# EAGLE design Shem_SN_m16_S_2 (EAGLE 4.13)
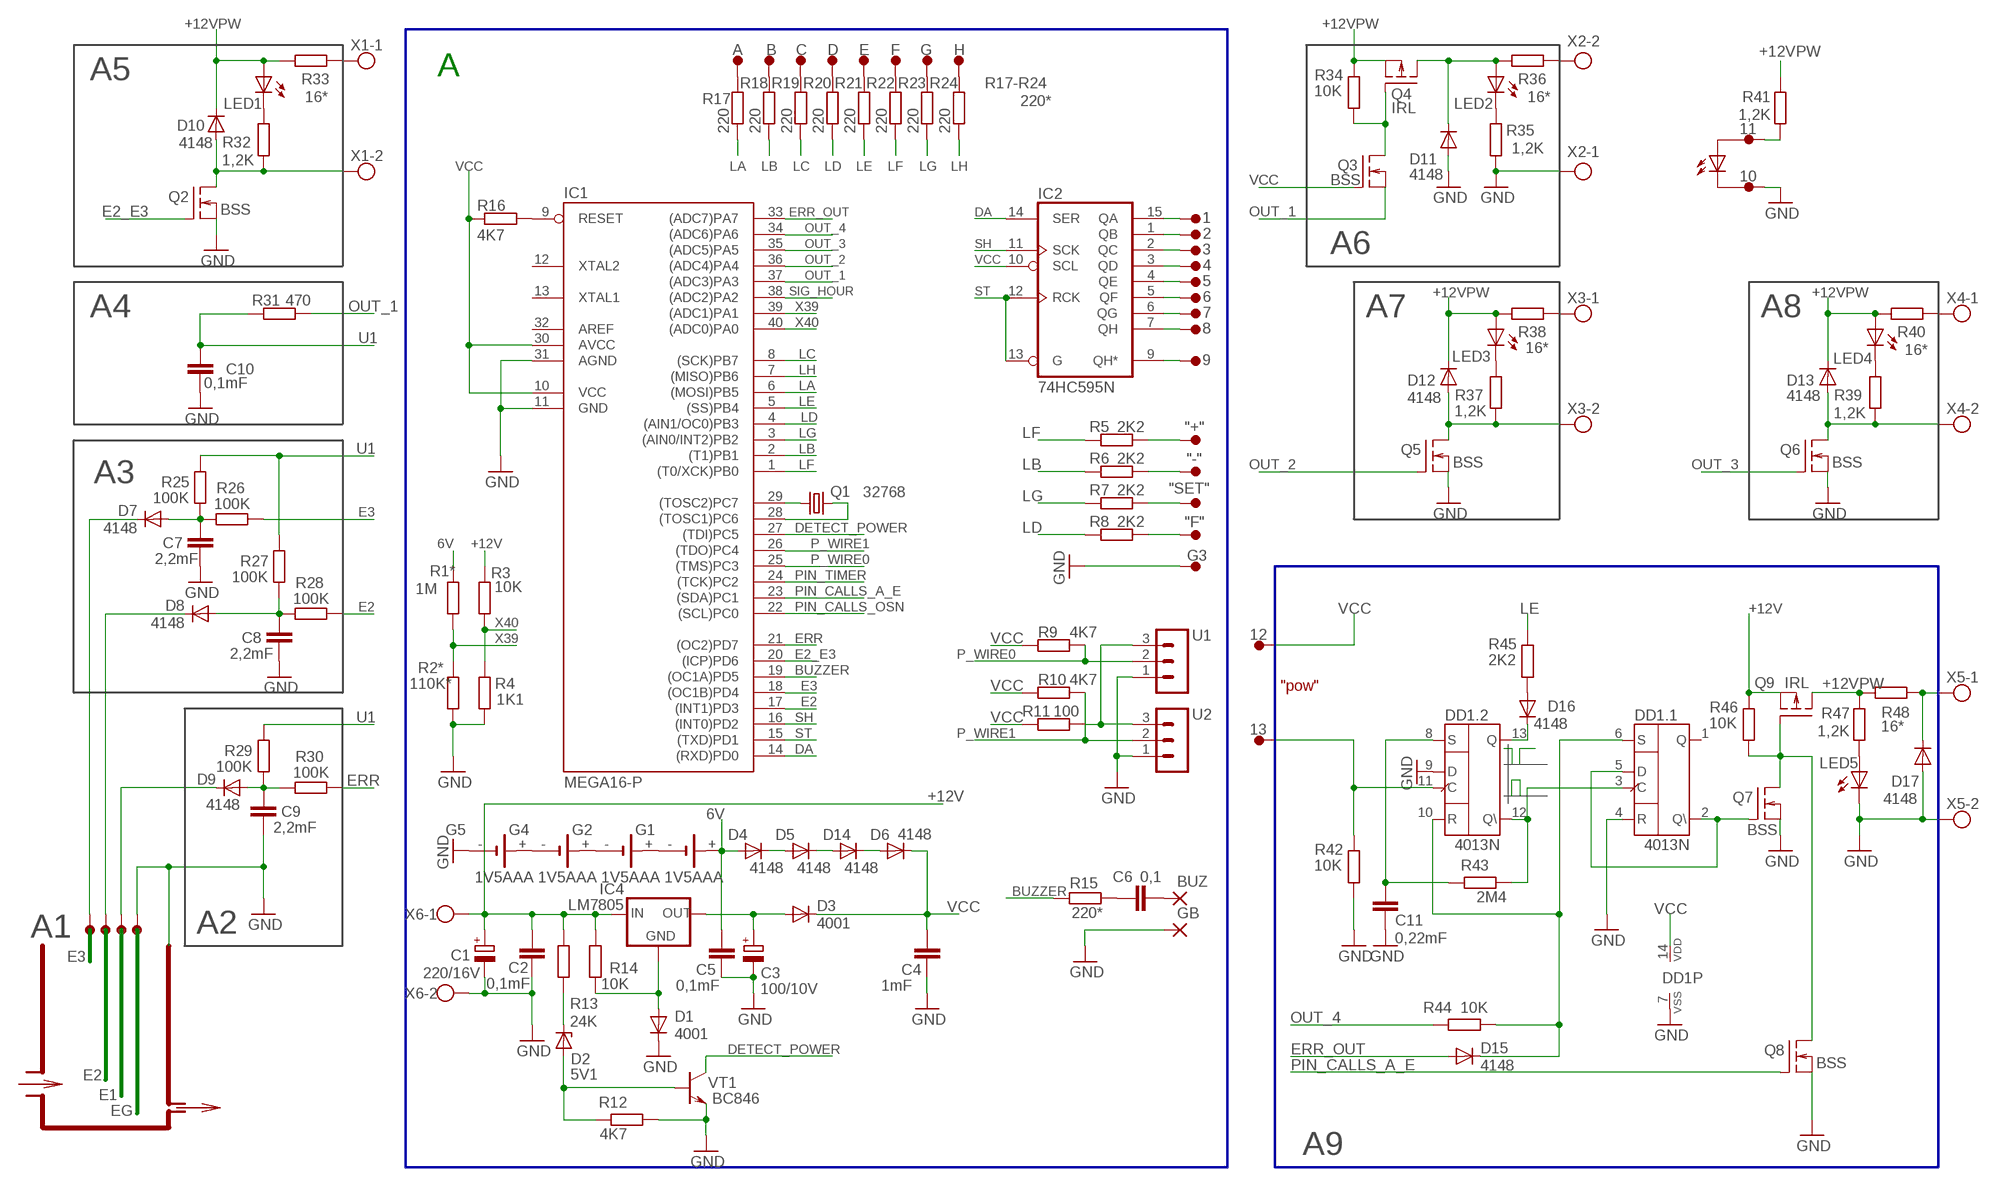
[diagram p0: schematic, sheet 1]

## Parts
1  2,0/0,8  [2,0/0,8]
2  2,0/0,8  [2,0/0,8]
3  2,0/0,8  [2,0/0,8]
4  2,0/0,8  [2,0/0,8]
5  2,0/0,8  [2,0/0,8]
6  2,0/0,8  [2,0/0,8]
7  2,0/0,8  [2,0/0,8]
8  2,0/0,8  [2,0/0,8]
9  2,0/0,8  [2,0/0,8]
10  2,0/0,8  [2,0/0,8]
11  2,0/0,8  [2,0/0,8]
12  2,0/0,8  [2,0/0,8]
13  2,0/0,8  [2,0/0,8]
"+"  2,0/0,8  [2,0/0,8]
"-"  2,0/0,8  [2,0/0,8]
"F"  2,0/0,8  [2,0/0,8]
"SET"  2,0/0,8  [2,0/0,8]
A  2,0/0,8  [2,0/0,8]
B  2,0/0,8  [2,0/0,8]
BUZ  2,15/1,0  [2,15/1,0]
C  2,0/0,8  [2,0/0,8]
C1  220/16V  CPOL-EUE2.5-5  [E2,5-5]
C2  0,1mF  C-EU050-024X044  [C050-024X044]
C3  100/10V  CPOL-EUE2.5-5  [E2,5-5]
C4  1mF  C-EU050-024X044  [C050-024X044]
C5  0,1mF  C-EU050-024X044  [C050-024X044]
C6  0,1  C-EU050-024X044  [C050-024X044]
C7  2,2mF  C-EU050-024X044  [C050-024X044]
C8  2,2mF  C-EU050-024X044  [C050-024X044]
C9  2,2mF  C-EU050-024X044  [C050-024X044]
C10  0,1mF  C-EU050-024X044  [C050-024X044]
C11  0,22mF  C-EU050-024X044  [C050-024X044]
D  2,0/0,8  [2,0/0,8]
D1  4001  [D041-7,62]
D2  5V1  BZX90  [DO34Z7]
D3  4001  [D041-7,62]
D4  4148  BAS15  [DO34-7]
D5  4148  BAS15  [DO34-7]
D6  4148  BAS15  [DO34-7]
D7  4148  BAS15  [DO34-7]
D8  4148  BAS15  [DO34-7]
D9  4148  BAS15  [DO34-7]
D10  4148  BAS15  [DO34-7]
D11  4148  BAS15  [DO34-7]
D12  4148  BAS15  [DO34-7]
D13  4148  BAS15  [DO34-7]
D14  4148  BAS15  [DO34-7]
D15  4148  BAS15  [DO34-7]
D16  4148  BAS15  [DO34-7]
D17  4148  BAS15  [DO34-7]
DD1  4013N  [DIL14]
E  2,0/0,8  [2,0/0,8]
E1  2,15/0,8  [2,15/1,0]
E2  2,15/0,8  [2,15/1,0]
E3  2,15/0,8  [2,15/1,0]
EG  2,15/0,8  [2,15/1,0]
F  2,0/0,8  [2,0/0,8]
G  2,0/0,8  [2,0/0,8]
G1  1V5AAA  [R1,5GAAA]
G2  1V5AAA  [R1,5GAAA]
G3  2,0/0,8  [2,0/0,8]
G4  1V5AAA  [R1,5GAAA]
G5  1V5AAA  [R1,5GAAA]
GB  2,15/1,0  [2,15/1,0]
H  2,0/0,8  [2,0/0,8]
IC1  MEGA16-P  [DIL40]
IC2  74HC595N  [DIL16]
IC4  LM7805  78XXL  [78XXL]
LED1  LED3MM  [LED3MM]
LED2  LED3MM  [LED3MM]
LED3  LED3MM  [LED3MM]
LED4  LED3MM  [LED3MM]
LED5  LED3MM  [LED3MM]
Q1  32768  CRYSTALTC26V  [TC26V]
Q2  BSS  MOSFET-NGSD  [MICRO3]
Q3  BSS  MOSFET-NGSD  [MICRO3]
Q4  IRL  MOSFET-PGSD  [MICRO3]
Q5  BSS  MOSFET-NGSD  [MICRO3]
Q6  BSS  MOSFET-NGSD  [MICRO3]
Q7  BSS  MOSFET-NGSD  [MICRO3]
Q8  BSS  MOSFET-NGSD  [MICRO3]
Q9  IRL  MOSFET-PGSD  [MICRO3]
R1*  1M  R0.25-10.16  [0.25W-10.16]
R2*  110K*  R0.25-10.16  [0.25W-10.16]
R3  10K  R0.25-10.16  [0.25W-10.16]
R4  1K1  R0.25-10.16  [0.25W-10.16]
R5  2K2  R0.25-10.16  [0.25W-10.16]
R6  2K2  R0.25-10.16  [0.25W-10.16]
R7  2K2  R0.25-10.16  [0.25W-10.16]
R8  2K2  R0.25-10.16  [0.25W-10.16]
R9  4K7  R0.25-10.16  [0.25W-10.16]
R10  4K7  R0.25-10.16  [0.25W-10.16]
R11  100  R0.25-10.16  [0.25W-10.16]
R12  4K7  R0.25-10.16  [0.25W-10.16]
R13  24K  R0.25-10.16  [0.25W-10.16]
R14  10K  R0.25-10.16  [0.25W-10.16]
R15  220*  R0.25-10.16  [0.25W-10.16]
R16  4K7  R0.25-10.16  [0.25W-10.16]
R17  220  R0.25-10.16  [0.25W-10.16]
R18  220  R0.25-10.16  [0.25W-10.16]
R19  220  R0.25-10.16  [0.25W-10.16]
R20  220  R0.25-10.16  [0.25W-10.16]
R21  220  R0.25-10.16  [0.25W-10.16]
R22  220  R0.25-10.16  [0.25W-10.16]
R23  220  R0.25-10.16  [0.25W-10.16]
R24  220  R0.25-10.16  [0.25W-10.16]
R25  100K  R0.25-10.16  [0.25W-10.16]
R26  100K  R0.25-10.16  [0.25W-10.16]
R27  100K  R0.25-10.16  [0.25W-10.16]
R28  100K  R0.25-10.16  [0.25W-10.16]
R29  100K  R0.25-10.16  [0.25W-10.16]
R30  100K  R0.25-10.16  [0.25W-10.16]
R31  470  R0.25-10.16  [0.25W-10.16]
R32  1,2K  R0.25-10.16  [0.25W-10.16]
R33  16*  R0.25-10.16  [0.25W-10.16]
R34  10K  R0.25-10.16  [0.25W-10.16]
R35  1,2K  R0.25-10.16  [0.25W-10.16]
R36  16*  R0.25-10.16  [0.25W-10.16]
R37  1,2K  R0.25-10.16  [0.25W-10.16]
R38  16*  R0.25-10.16  [0.25W-10.16]
R39  1,2K  R0.25-10.16  [0.25W-10.16]
R40  16*  R0.25-10.16  [0.25W-10.16]
R41  1,2K  R0.25-10.16  [0.25W-10.16]
R42  10K  R0.25-10.16  [0.25W-10.16]
R43  2M4  R0.25-10.16  [0.25W-10.16]
R44  10K  R0.25-10.16  [0.25W-10.16]
R45  2K2  R0.25-10.16  [0.25W-10.16]
R46  10K  R0.25-10.16  [0.25W-10.16]
R47  1,2K  R0.25-10.16  [0.25W-10.16]
R48  16*  R0.25-10.16  [0.25W-10.16]
U1  MA03-1  [MA03-1]
U2  MA03-1  [MA03-1]
VT1  BC846  NPN23-BEC  [SOT23]
X1  W237-02P  [W237-132]
X2  W237-02P  [W237-132]
X3  W237-02P  [W237-132]
X4  W237-02P  [W237-132]
X5  W237-02P  [W237-132]
X6  W237-02P  [W237-132]

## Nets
6V: C5.1 D4.A G1.+ R1*.2
+12V: C1.+ C2.1 IC4.IN Q9.2(S) R3.2 R13.2 R14.2 R46.2 X6.1
+12VPW: D10.C D12.C D13.C LED1.A LED3.A LED4.A Q4.2(S) Q9.3(D) R33.1 R34.2 R38.1 R40.1 R41.2 R47.2 R48.2
A: A.1(P) R17.1
B: B.1(P) R18.1
BUZZER: IC1.19((OC1A)PD5) R15.1
C: C.1(P) R19.1
D: D.1(P) R20.1
DA: IC1.14((RXD)PD0) IC2.14(SER)
DETECT_POWER: IC1.27((TDI)PC5) VT1.3(C)
E: E.1(P) R21.1
E2: IC1.17((INT1)PD3) R28.1
E2_E3: IC1.20((ICP)PD6) Q2.1(G)
E3: IC1.18((OC1B)PD4) R26.1
ERR: IC1.21((OC2)PD7) R30.1
ERR_OUT: D15.A IC1.33((ADC7)PA7)
F: F.1(P) R22.1
G: G.1(P) R23.1
GND: 10.1(P) C1.- C2.2 C3.- C4.2 C5.2 C7.1 C8.1 C9.1 C10.1 C11.1 D1.C D11.A D17.A DD1.4(.1:R) DD1.7(P:VSS) DD1.9(.2:D) EG.1(P) G3.1(P) G5.- GB.1(P) IC1.11(GND) IC1.31(AGND) LED5.K(C) Q2.2(S) Q5.2(S) Q6.2(S) Q7.2(S) Q8.2(S) R2*.1 R4.1 R12.1 R35.1 R42.1 U1.1 U2.1 VT1.2(E) X2.1 X5.2 X6.2
H: H.1(P) R24.1
I1: 1.1(P) IC2.15(QA)
I2: 2.1(P) IC2.1(QB)
I3: 3.1(P) IC2.2(QC)
I4: 4.1(P) IC2.3(QD)
I5: 5.1(P) IC2.4(QE)
I6: 6.1(P) IC2.5(QF)
I7: 7.1(P) IC2.6(QG)
I8: 8.1(P) IC2.7(QH)
I9: 9.1(P) IC2.9(QH*)
LA: IC1.6((MOSI)PB5) R17.2
LB: IC1.2((T1)PB1) R6.2 R18.2
LC: IC1.8((SCK)PB7) R19.2
LD: IC1.4((AIN1/OC0)PB3) R8.2 R20.2
LE: IC1.5((SS)PB4) R21.2 R45.2
LF: IC1.1((T0/XCK)PB0) R5.2 R22.2
LG: IC1.3((AIN0/INT2)PB2) R7.2 R23.2
LH: IC1.7((MISO)PB6) R24.2
N$1: "-".1(P) R6.1
N$2: "+".1(P) R5.1
N$3: "SET".1(P) R7.1
N$4: C6.1 R15.2
N$5: BUZ.1(P) C6.2
N$6: G1.- G2.+
N$7: LED1.K(C) R32.2
N$8: LED2.K(C) R35.2
N$9: "F".1(P) R8.1
N$10: R11.1 U1.3 U2.3
N$11: IC1.28((TOSC1)PC6) Q1.2
N$12: G2.- G4.+
N$13: IC1.29((TOSC2)PC7) Q1.1
N$14: D4.C D5.A
N$15: D6.A D14.C
N$16: LED3.K(C) R37.2
N$17: D2.A R12.2 VT1.1(B)
N$18: D2.C R13.1
N$19: LED4.K(C) R39.2
N$20: C8.2 D8.A R27.2 R28.2
N$21: D1.A IC4.GND R14.1
N$23: C7.2 D7.A R25.2 R26.2
N$24: C3.+ D3.A IC4.OUT
N$25: IC1.9(RESET) R16.2
N$26: C9.2 D9.A R29.2 R30.2
N$27: D9.C E1.1(P)
N$28: D8.C E2.1(P)
N$29: D7.C E3.1(P)
N$30: D10.A Q2.3(D) R32.1 X1.2
N$31: D12.A Q5.3(D) R37.1 X3.2
N$32: D13.A Q6.3(D) R39.1 X4.2
N$34: C11.2 DD1.8(.2:S) R43.1
N$35: DD1.3(.1:C) DD1.12(.2:Q\) R43.2
N$36: DD1.2(.1:Q\) DD1.5(.1:D) Q7.1(G)
N$37: D16.C DD1.13(.2:Q)
N$38: D15.C DD1.6(.1:S) DD1.10(.2:R) R44.2
N$39: 11.1(P) R41.1
N$40: R33.2 X1.1
N$41: Q3.3(D) Q4.1(G) R34.1
N$42: D11.C LED2.A Q4.3(D) R36.1
N$43: 13.1(P) DD1.11(.2:C) R42.2
N$44: LED5.A R47.1
N$45: Q7.3(D) Q8.3(D) Q9.1(G) R46.1
N$46: R36.2 X2.2
N$47: R38.2 X3.1
N$48: D16.A R45.1
N$49: R40.2 X4.1
N$50: D17.C R48.1 X5.1
N$51: G4.- G5.+
N$52: D5.C D14.A
OUT_1: IC1.37((ADC3)PA3) Q3.2(S) R31.1
OUT_2: IC1.36((ADC4)PA4) Q5.1(G)
OUT_3: IC1.35((ADC5)PA5) Q6.1(G)
OUT_4: IC1.34((ADC6)PA6) R44.1
P_WIRE0: IC1.25((TMS)PC3) R9.1 U1.2
P_WIRE1: IC1.26((TDO)PC4) R10.1 U2.2
PIN_CALLS_A_E: IC1.23((SDA)PC1) Q8.1(G)
PIN_CALLS_OSN: IC1.22((SCL)PC0)
PIN_TIMER: IC1.24((TCK)PC2)
SH: IC1.16((INT0)PD2) IC2.11(SCK)
SIG_HOUR: IC1.38((ADC2)PA2)
ST: IC1.15((TXD)PD1) IC2.12(RCK) IC2.13(G)
U1: C10.2 R25.1 R27.1 R29.1 R31.2
VCC: 12.1(P) C4.1 D3.C D6.C DD1.14(P:VDD) IC1.10(VCC) IC1.30(AVCC) IC2.10(SCL) Q3.1(G) R9.2 R10.2 R11.2 R16.1
X39: IC1.39((ADC1)PA1) R1*.1 R2*.2
X40: IC1.40((ADC0)PA0) R3.1 R4.2
Unconnected: DD1.1(.1:Q) IC1.12(XTAL2) IC1.13(XTAL1)

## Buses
B$1
B$2

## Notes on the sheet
- A5 | A
- R17-R24
- 220*
- A6
- A4 | A7 | A8
- A3
- "pow"
- A1 | A2
- A9

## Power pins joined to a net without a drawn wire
AREF: IC1.32(AREF)
GND: IC2.8(GND)
VCC: IC2.16(VCC)

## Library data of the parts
1-13 "+" "-" "F" "SET" A B C D E F G G3 H = wirepad:2,0/0,8: THROUGH-HOLE PAD
BUZ GB = wirepad:2,15/1,0: THROUGH-HOLE PAD
C1 C3 = rcl:CPOL-EU: POLARIZED CAPACITOR, European symbol
C2 C4-C11 = rcl:C-EU: CAPACITOR, European symbol
D1 D3 = 3:4001: DIODE
D2 = diode:BZX90: Z DIODE
D4-D17 = diode:BAS15: DIODE
DD1 = 40xx_:4013: Dual D FLIP FLOP, set/reset
E1-E3 EG = wirepad:2,15/0,8: THROUGH-HOLE PAD
G1 G2 G4 G5 = battery_:1V5AAA: NC AAA
IC1 = atmel:MEGA16-P: MICROCONTROLLER 16 Kbytes FLASH 1 kbytes SRAM 512 bytes EEPROM USART 8-channel 10 bit ADC Source: avr.lbr
IC2 = 74xx-eu:74*595: 8-bit SHIFT REGISTER, output latch
IC4 = v-reg:78XXL: VOLTAGE REGULATOR
LED1-LED5 = led:LED: LED
Q1 = crystal:CRYSTAL: CRYSTAL
Q2 Q3 Q5-Q8 = 1TRANSISTOR_p:MOSFET-N: Power MOSFET
Q4 Q9 = 1TRANSISTOR_p:MOSFET-P: Power MOSFET
R1* R2* R3-R48 = 1RC:R: RESISTOR
U1 U2 = con-lstb:MA03-1: PIN HEADER
VT1 = 1TRANSISTOR_p:NPN: NPN TRANSISTOR
X1-X6 = con-wago-508:W237-02P: WAGO SREW CLAMP

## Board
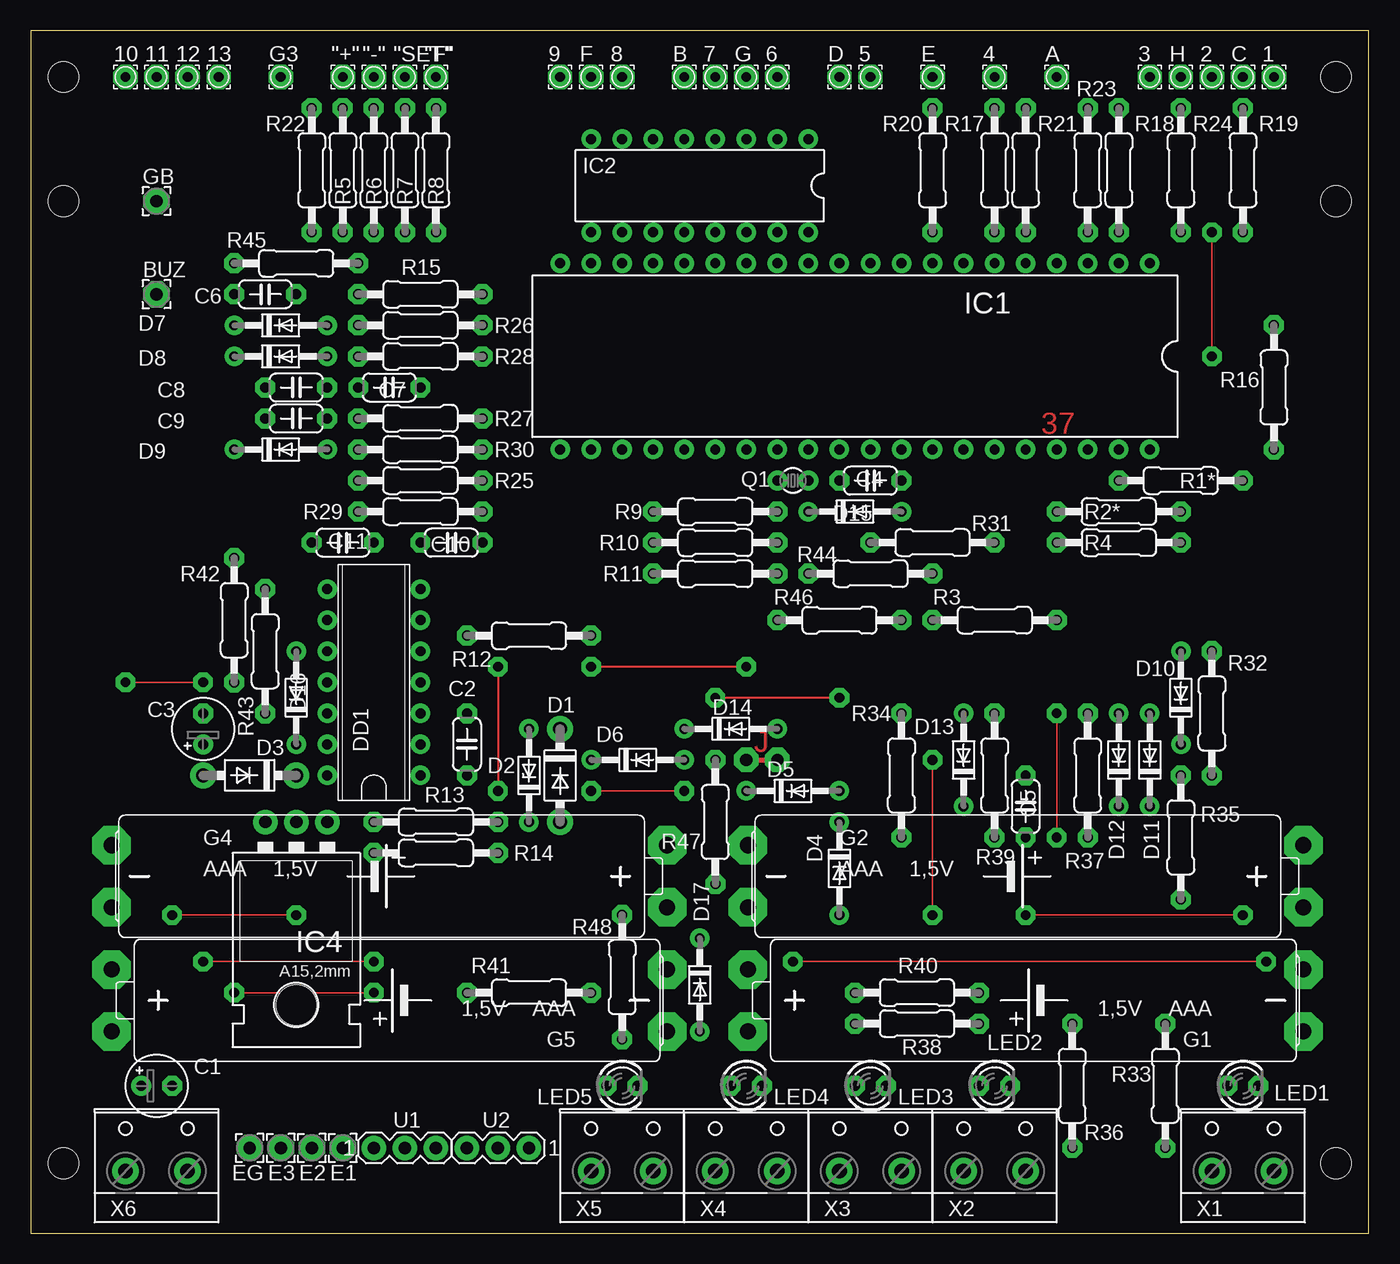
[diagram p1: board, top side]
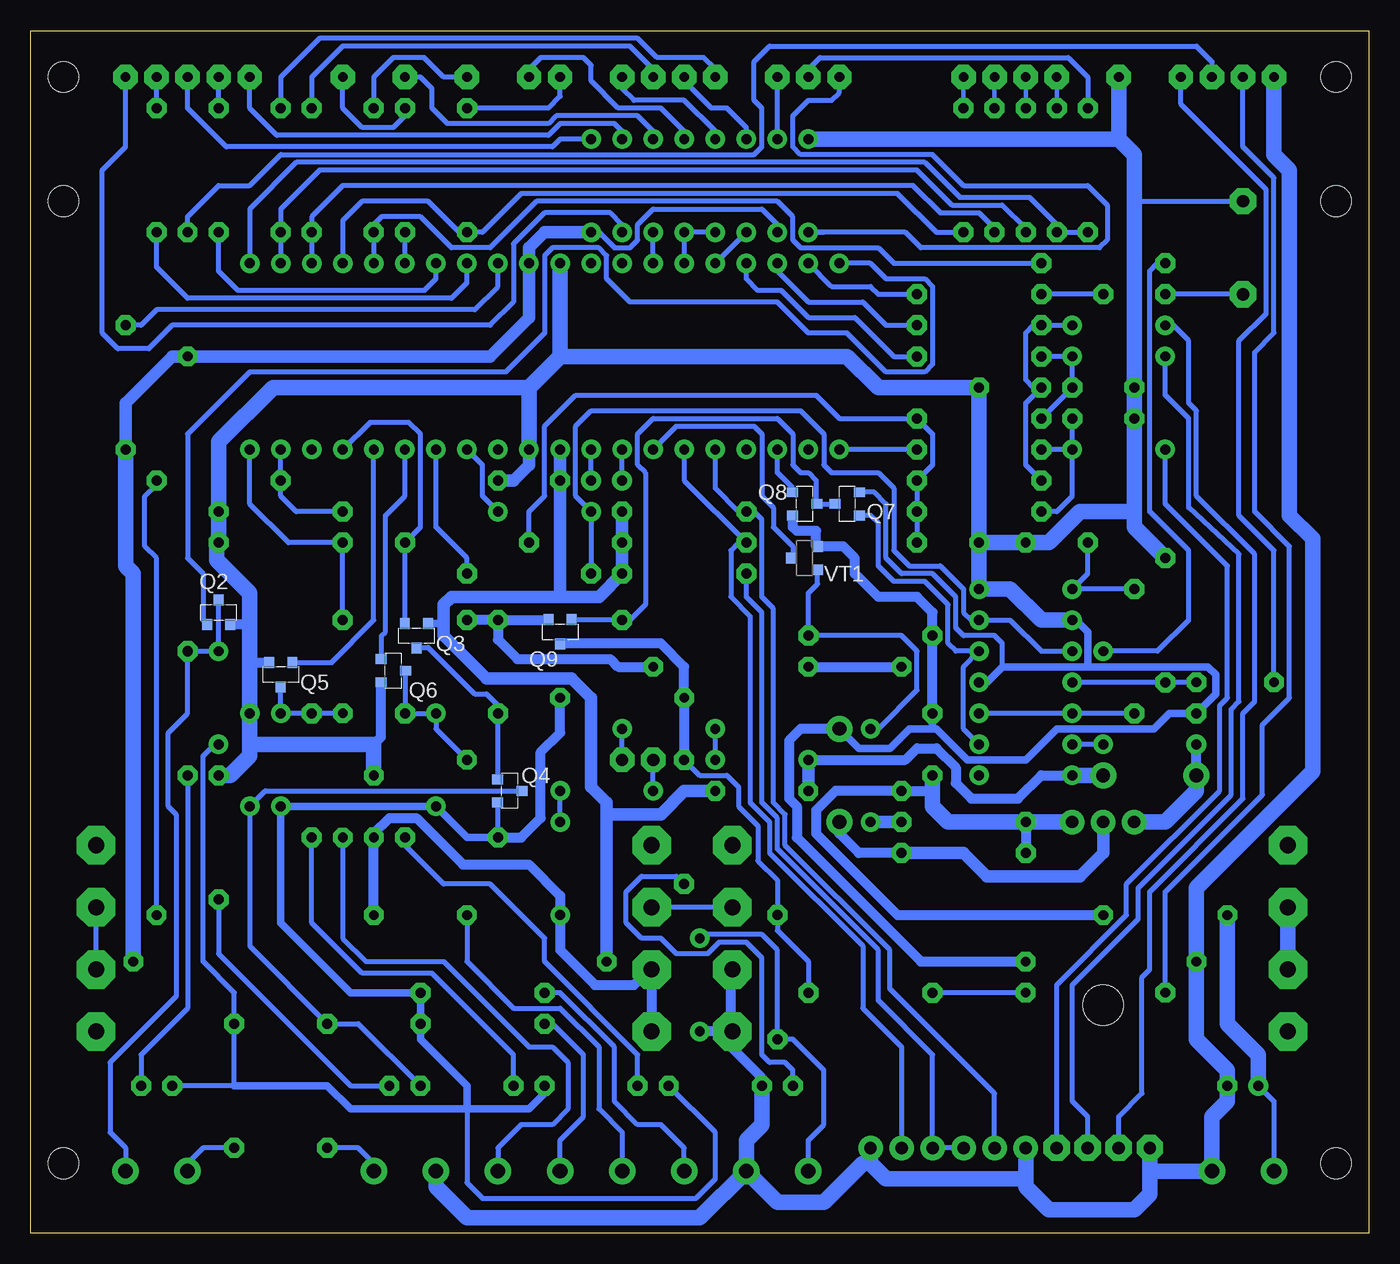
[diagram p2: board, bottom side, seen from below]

Size 109.52 x 98.42 mm. Coordinates in mm from the lower left corner, seen from the top.
Outline: 0,0 109.52,0 109.52,98.42 0,98.42 0,0
Copper layers (1*16): Top 0.035mm / dielectric 1.5mm / Bottom 0.035mm
Design rules "default": minimum track width 16mil, minimum drill 24mil, track to track 14mil, track to pad 8mil, pad to pad 8mil, via to via 8mil, smd to smd 8mil, copper to edge 0mil, drill to drill 8mil, minimum pad ring 10mil, minimum via ring 8mil, stop-mask expansion 4mil, vias tented up to drill 0mil, thermal gap 10mil
Holes 2.5 mm at 2.69,94.61 106.83,94.61 106.83,5.71 2.69,5.71 2.69,84.45 106.83,84.45

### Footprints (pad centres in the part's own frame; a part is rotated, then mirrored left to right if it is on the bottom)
2,0/0,8 = drill 0.8 pad 2 octagon: 1 0,0
2,15/1,0 = drill 1.016 pad 2.159 octagon: 1 0,0
E2,5-5 = drill 0.813 pad 1.6 round: + -1.27,0 | drill 0.813 pad 1.6 octagon: - 1.27,0
C050-024X044 = drill 0.813 octagon: 1 -2.54,0; 2 2.54,0
D041-7,62 = drill 1.118 round: A 3.81,0; C -3.81,0
DO34Z7 = drill 0.813 long: A 3.81,0; C -3.81,0
DO34-7 = drill 0.813 long: A 3.81,0; C -3.81,0
DIL14 = drill 0.813 long: 1 -7.62,-3.81; 2 -5.08,-3.81; 3 -2.54,-3.81; 4 0,-3.81; 5 2.54,-3.81; 6 5.08,-3.81; 7 7.62,-3.81; 8 7.62,3.81; 9 5.08,3.81; 10 2.54,3.81; 11 0,3.81; 12 -2.54,3.81; 13 -5.08,3.81; 14 -7.62,3.81
R1,5GAAA = drill 1.321 pad 3.15 octagon: + 23.36,-2.54; +@1 23.36,2.54; - -22.09,-2.54; -@1 -22.09,2.54
DIL40 = drill 0.813 long: 1 -24.13,-7.62; 2 -21.59,-7.62; 3 -19.05,-7.62; 4 -16.51,-7.62; 5 -13.97,-7.62; 6 -11.43,-7.62; 7 -8.89,-7.62; 8 -6.35,-7.62; 9 -3.81,-7.62; 10 -1.27,-7.62; 11 1.27,-7.62; 12 3.81,-7.62; 13 6.35,-7.62; 14 8.89,-7.62; 15 11.43,-7.62; 16 13.97,-7.62; 17 16.51,-7.62; 18 19.05,-7.62; 19 21.59,-7.62; 20 24.13,-7.62; 21 24.13,7.62; 22 21.59,7.62; 23 19.05,7.62; 24 16.51,7.62; 25 13.97,7.62; 26 11.43,7.62; 27 8.89,7.62; 28 6.35,7.62; 29 3.81,7.62; 30 1.27,7.62; 31 -1.27,7.62; 32 -3.81,7.62; 33 -6.35,7.62; 34 -8.89,7.62; 35 -11.43,7.62; 36 -13.97,7.62; 37 -16.51,7.62; 38 -19.05,7.62; 39 -21.59,7.62; 40 -24.13,7.62
DIL16 = drill 0.813 long: 1 -8.89,-3.81; 2 -6.35,-3.81; 3 -3.81,-3.81; 4 -1.27,-3.81; 5 1.27,-3.81; 6 3.81,-3.81; 7 6.35,-3.81; 8 8.89,-3.81; 9 8.89,3.81; 10 6.35,3.81; 11 3.81,3.81; 12 1.27,3.81; 13 -1.27,3.81; 14 -3.81,3.81; 15 -6.35,3.81; 16 -8.89,3.81
78XXL = drill 1.016 long: GND 0,-3.81; IN -2.54,-3.81; OUT 2.54,-3.81 | hole 3.302: 0,11.176
LED3MM = drill 0.813 octagon: A -1.27,0; K 1.27,0
TC26V = drill 0.813 round: 1 -1.27,0; 2 1.27,0
MICRO3 = smd 0.8 x 0.9: 1 -0.95,-1; 2 0.95,-1; 3 0,1
0.25W-10.16 = drill 0.82 octagon: 1 -5.08,0; 2 5.08,0
MA03-1 = drill 1.016 long: 1 -2.54,0; 2 0,0; 3 2.54,0
SOT23 = smd 0.889 x 0.889: 1 -0.95,-1.069; 2 0.95,-1.069; 3 0,1.069
W237-132 = drill 1.194 long: 1 -2.54,-0.635; 2 2.54,-0.635

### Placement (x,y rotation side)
1  101.75,94.61 0 top
2  96.67,94.61 0 top
3  91.59,94.61 0 top
4  78.89,94.61 0 top
5  68.73,94.61 0 top
6  61.11,94.61 0 top
7  56.03,94.61 0 top
8  48.41,94.61 0 top
9  43.33,94.61 0 top
10  7.77,94.61 0 top
11  10.31,94.61 0 top
12  12.85,94.61 0 top
13  15.39,94.61 0 top
"+"  25.55,94.61 0 top
"-"  28.09,94.61 0 top
"F"  33.17,94.61 0 top
"SET"  30.63,94.61 0 top
A  83.97,94.61 0 top
B  53.49,94.61 0 top
BUZ  10.31,76.83 0 top
C  99.21,94.61 0 top
C1  10.31,12.06 0 top
C2  35.71,40 90 top
C3  14.12,41.27 90 top
C4  68.73,61.59 0 top
C5  81.43,34.92 90 top
C6  19.2,76.83 180 top
C7  29.36,69.21 180 top
C8  21.74,69.21 0 top
C9  21.74,66.67 0 top
C10  34.44,56.51 0 top
C11  25.55,56.51 180 top
D  66.19,94.61 0 top
D1  43.33,37.46 270 top
D2  40.79,37.46 90 top
D3  17.93,37.46 180 top
D4  66.19,29.84 270 top
D5  62.38,36.19 0 top
D6  49.68,38.73 0 top
D7  20.47,74.29 0 top
D8  20.47,71.75 0 top
D9  20.47,64.13 0 top
D10  94.13,43.81 90 top
D11  91.59,38.73 90 top
D12  89.05,38.73 90 top
D13  76.35,38.73 90 top
D14  57.3,41.27 0 top
D15  67.46,59.05 0 top
D16  21.74,43.81 90 top
D17  54.76,20.32 270 top
DD1  28.09,45.08 90 top
E  73.81,94.61 0 top
E1  25.55,6.98 180 top
E2  23.01,6.98 180 top
E3  20.47,6.98 180 top
EG  17.93,6.98 180 top
F  45.87,94.61 0 top
G  58.57,94.61 0 top
G1  82.07,19.04 180 top
G2  80.8,29.21 0 top
G3  20.47,94.61 0 top
G4  28.73,29.21 0 top
G5  30,19.04 180 top
GB  10.31,84.45 0 top
H  94.13,94.61 0 top
IC1  67.46,71.75 180 top
IC2  54.76,85.72 180 top
IC4  21.74,29.84 180 top
LED1  99.21,12.06 0 top
LED2  78.89,12.06 0 top
LED3  68.73,12.06 0 top
LED4  58.57,12.06 0 top
LED5  48.41,12.06 0 top
Q1  62.38,61.59 180 top
Q2  94.13,50.79 0 bottom
Q3  77.94,48.89 180 bottom
Q4  70.32,36.19 270 bottom
Q5  89.05,45.71 180 bottom
Q6  79.85,46.03 270 bottom
Q7  42.7,59.68 90 bottom
Q8  46.19,59.68 270 bottom
Q9  66.19,49.21 180 bottom
R1*  94.13,61.59 0 top
R2*  89.05,59.05 180 top
R3  78.89,50.16 180 top
R4  89.05,56.51 180 top
R5  25.55,86.99 270 top
R6  28.09,86.99 270 top
R7  30.63,86.99 270 top
R8  33.17,86.99 270 top
R9  56.03,59.05 0 top
R10  56.03,56.51 0 top
R11  56.03,53.97 0 top
R12  40.79,48.89 0 top
R13  33.17,33.65 180 top
R14  33.17,31.11 180 top
R15  31.9,76.83 180 top
R16  101.75,69.21 90 top
R17  78.89,86.99 270 top
R18  89.05,86.99 270 top
R19  99.21,86.99 270 top
R20  73.81,86.99 270 top
R21  81.43,86.99 270 top
R22  23.01,86.99 270 top
R23  86.51,86.99 270 top
R24  94.13,86.99 270 top
R25  31.9,61.59 180 top
R26  31.9,74.29 180 top
R27  31.9,66.67 180 top
R28  31.9,71.75 180 top
R29  31.9,59.05 180 top
R30  31.9,64.13 180 top
R31  73.81,56.51 180 top
R32  96.67,42.54 270 top
R33  92.86,12.06 270 top
R34  71.27,37.46 270 top
R35  94.13,32.38 270 top
R36  85.24,12.06 270 top
R37  86.51,37.46 270 top
R38  72.54,17.14 180 top
R39  78.89,37.46 270 top
R40  72.54,19.68 180 top
R41  40.79,19.68 0 top
R42  16.66,50.16 270 top
R43  19.2,47.62 270 top
R44  68.73,53.97 180 top
R45  21.74,79.37 0 top
R46  66.19,50.16 0 top
R47  56.03,33.65 90 top
R48  48.41,20.95 90 top
U1  30.63,6.98 0 top
U2  38.25,6.98 180 top
VT1  46.19,55.24 90 bottom
X1  99.21,5.71 0 top
X2  78.89,5.71 0 top
X3  68.73,5.71 0 top
X4  58.57,5.71 0 top
X5  48.41,5.71 0 top
X6  10.31,5.71 0 top

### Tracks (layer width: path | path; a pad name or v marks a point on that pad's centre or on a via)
6V  (via drill 0.8)
  Top 0.127: v99.21,26.03 v81.43,26.03
  Bottom 0.406: R1*.2 99.21,61.27 100.17,60.32 100.17,56.19 99.21,55.24 v99.21,26.03
  Bottom 0.813: 58.57,16.51 58.71,16.64 G1.+ 58.89,21.59 60.16,20.32 63.33,20.32 66.19,23.17 D4.A | D4.A 66.19,26.35 | D4.A 66.19,27.62 68.73,30.16 74.13,30.16 77.94,33.97 80.16,33.97 81.43,32.7 C5.1 v81.43,26.03
+12V  (via drill 0.8)
  Top 0.127: v21.74,26.03 v11.58,26.03
  Top 0.152: v38.25,46.35 v38.25,36.19 | v58.57,46.35 v45.87,46.35
  Bottom 0.406: X6.1 7.77,10.79 C1.+ | R46.2 71.27,50.21
  Bottom 0.813: R13.2 R14.2 | 35.71,36.19 v38.25,36.19 43.65,36.19 45.24,34.6 45.24,32.7 38.57,26.03 v21.74,26.03 | R46.2 71.27,48.57 69.68,46.99 62.07,46.99 61.43,46.35 v58.57,46.35 | R46.2 R3.2 | Q9.2 67.14,50.16 R46.2 | v45.87,46.35 v38.25,46.35
  Bottom 1.27: C2.1 35.71,36.19 35.71,34.92 34.44,33.65 R13.2 IC4.IN | C1.+ 9.04,14.6 11.58,17.14 v11.58,26.03
+12VPW  (via drill 0.8)
  Top 0.152: v66.19,43.81 v56.03,43.81
  Bottom 0.406: 93.82,40 D10.C 94.45,40 95.4,39.05 95.4,22.22 92.86,19.68 R33.1 92.86,12.06 LED1.A | Q4.2 71.27,35.24 R34.2 | LED4.A 53.49,8.25 53.49,4.44 55.08,2.85 72.54,2.85 73.81,4.12 73.81,10.15 | Q9.3 66.19,48.26 | R47.2 54.76,37.46 52.54,37.46 51.59,36.51 51.59,34.92 50,33.33 50,30.48 48.41,28.89 R48.2 48.41,24.76 45.87,22.22 R41.2
  Bottom 0.61: R34.2 73.81,32.38 D13.C D12.C 89.05,25.4 83.34,19.68 R40.1 R38.1 77.62,15.87 73.81,12.06 73.81,10.15 | LED3.A 67.46,11.43 68.73,10.15 73.81,10.15 | 92.86,12.06 85.24,12.06 83.34,10.15 73.81,10.15
  Bottom 0.813: v66.19,43.81 66.19,40.95 67.78,39.37 67.78,33.97 69.37,32.38 R34.2 | Q9.3 65.92,48.21 65.88,48.26 57.94,48.26 56.03,46.35 v56.03,43.81 R47.2
A
  Bottom 0.406: A.1 83.97,92.07 82.39,90.48 79.85,90.48 78.89,91.44 R17.1
B
  Bottom 0.406: B.1 53.49,95.25 54.45,96.2 58.26,96.2 59.84,97.78 85.88,97.78 89.05,94.61 89.05,92.39 89.37,92.07 R18.1
BUZZER
  Bottom 0.406: R15.1 40.16,76.83 40.79,77.47 43.97,77.47 IC1.19
C
  Bottom 0.406: R19.1 C.1
D
  Bottom 0.406: D.1 66.19,93.02 67.14,92.07 R20.1
DA
  Bottom 0.406: IC1.14 IC2.14
DETECT_POWER
  Bottom 0.406: IC1.27 56.67,66.03 50.32,66.03 49.68,65.4 49.68,60.32 48.73,59.37 48.73,57.78 47.14,56.19 47.14,55.56 47.26,55.44 VT1.3
E
  Bottom 0.406: E.1 75.72,94.61 77.3,96.2 79.85,96.2 81.43,94.61 R21.1
E2
  Bottom 0.406: IC1.17 50.95,78.1 50,77.15 48.09,77.15 45.87,74.93 42.06,74.93 38.89,71.75 R28.1
E2_E3
  Bottom 0.406: IC1.20 40.79,79.37 39.52,78.1 36.35,78.1 35.71,77.47 35.71,71.12 36.35,70.48 39.52,70.48 42.7,73.66 45.87,73.66 48.41,76.2 60.48,76.2 62.38,78.1 62.38,80 63.02,80.64 66.83,80.64 67.46,80 67.46,73.66 70.64,70.48 91.59,70.48 96.67,65.4 96.67,55.24 95.4,53.97 95.4,50.16 95.08,49.84 Q2.1
E3
  Bottom 0.406: R26.1 39.52,74.29 41.43,76.2 45.87,76.2 48.41,78.74 IC1.18
ERR
  Bottom 0.406: R30.1 IC1.21
ERR_OUT
  Bottom 0.406: D15.A 72.54,60.32 72.54,62.86 IC1.33
F
  Bottom 0.406: R22.1 23.01,94.61 24.6,96.2 44.92,96.2 45.87,95.25 F.1
G
  Bottom 0.406: G.1 58.57,95.25 60.48,97.15 83.97,97.15 86.51,94.61 R23.1
GND  (via drill 0.8)
  Top 0.127: v28.09,22.22 v14.12,22.22
  Bottom 0.406: 30,46.35 30,48.26 30.63,48.89 33.17,48.89 33.81,49.52 33.81,52.07 35.71,53.97 38.25,53.97 39.52,55.24 39.52,59.68 40.47,60.64 41.75,60.64 41.74,60.63 Q7.2 | 19.2,84.45 GB.1 | 94.3,56.34 R4.1
  Bottom 0.61: D1.C 41.75,39.68 39.2,39.68 37.62,41.27 35.71,41.27 | 35.71,41.27 35.39,41.27 32.86,38.73 28.09,38.73 25.55,41.27 17.61,41.27 16.34,42.54 C3.- 12.53,44.13 12.53,45.71 13.17,46.35 23.01,46.35 | 35.71,41.27 C2.2 | 23.01,46.35 30,46.35 31.27,45.08 DD1.4 | DD1.9 23.97,50.16 23.01,49.21 23.01,46.35
  Bottom 0.813: C2.2 R12.1 35.71,50.79 36.98,52.07 40.16,52.07 42.06,53.97 42.06,55.24 43.01,56.19 VT1.2 45.24,56.19 45.24,57.46 46.83,57.46 47.14,57.78 47.14,58.73 47.14,58.74 Q8.2 | v28.09,22.22 36.67,22.22 46.83,32.38 46.83,34.92 47.46,35.55 47.46,40.32 46.51,41.27 D1.C | Q6.2 80.85,40.59 81.43,40 | Q5.2 91.55,46.71 91.59,46.67 | Q2.2 91.64,49.79 91.59,49.84 | LED5.K 49.68,12.7 52.22,15.24 52.22,16.51 | G5.- 52.22,21.59 52.22,16.51 | 52.22,16.51 D17.A
  Bottom 1.016: IC1.31 68.73,62.86 70,61.59 C4.2
  Bottom 1.27: 20.47,89.53 IC2.8 | 20.47,89.53 G3.1 | C9.1 19.2,84.45 19.2,88.26 20.47,89.53 | 66.19,71.75 IC1.11 | 68.73,69.21 66.19,71.75 | 68.73,69.21 IC1.31 | 66.19,71.75 42.7,71.75 40.16,69.21 C7.1 C10.1 | C9.1 C8.1 C9.1 | C10.1 DD1.7 29.36,52.7 26.82,50.16 DD1.9 | 68.73,69.21 89.69,69.21 94.13,64.77 R2*.1 R4.1 | C10.1 C11.1 26.19,56.51 23.65,59.05 19.2,59.05 | 91.59,40 81.43,40 C5.2 | 91.59,40 D11.A 91.59,46.67 91.59,49.84 91.59,52.38 94.3,55.09 94.3,56.34 | R42.1 19.2,57.78 19.2,59.05 | 19.2,59.05 C9.1 | R35.1 93.18,37.46 91.59,39.05 91.59,40 | 28.09,4.44 28.09,3.8 26.19,1.9 19.2,1.9 17.93,3.17 17.93,5.08 | 28.09,4.44 U1.1 | 40.79,5.71 U2.1 | 40.79,5.71 39.52,4.44 28.09,4.44 | 40.79,5.71 41.43,5.71 44.6,2.54 48.41,2.54 X5.2 | X5.2 50.95,7.62 49.68,8.88 LED5.K | X5.2 54.76,1.27 73.81,1.27 76.35,3.8 X2.1 | 17.93,5.08 EG.1 | 17.93,5.08 X6.2 12.85,9.52 11.58,10.79 C1.- 11.58,13.33 14.12,15.87 v14.12,22.22 14.12,28.25 4.6,37.78 4.6,56.83 6.5,58.73 6.5,86.99 7.77,88.26 10.1
H
  Bottom 0.406: R24.1 H.1
I1
  Bottom 0.406: IC2.15 61.11,82.55 62.07,83.5 67.46,83.5 70,80.96 70,76.2 71.91,74.29 97.94,74.29 99.85,72.39 102.39,72.39 103.66,73.66 103.66,86.99 101.75,88.9 1.1
I2
  Bottom 0.406: IC2.1 66.19,89.53 66.83,88.9 93.5,88.9 96.67,92.07 2.1
I3
  Bottom 0.406: IC2.2 61.11,90.17 61.75,90.8 66.19,90.8 67.14,89.85 89.37,89.85 91.59,92.07 3.1
I4
  Bottom 0.406: IC2.3 58.57,90.17 59.84,91.44 66.51,91.44 67.14,90.8 75.4,90.8 76.67,92.07 76.67,93.66 77.62,94.61 4.1
I5
  Bottom 0.406: IC2.4 56.03,90.17 57.94,92.07 61.43,92.07 63.65,94.29 63.65,95.56 64.29,96.2 67.78,96.2 68.73,95.25 5.1
I6
  Bottom 0.406: IC2.5 53.49,90.17 56.03,92.71 60.16,92.71 61.11,93.66 6.1
I7
  Bottom 0.406: IC2.6 50.95,90.48 52.54,92.07 53.81,92.07 56.03,94.29 7.1
I8
  Bottom 0.406: IC2.7 8.1
I9
  Bottom 0.406: 9.1 43.33,93.34 43.97,92.71 45.87,92.71 47.14,91.44 47.14,88.9 46.51,88.26 35.71,88.26 33.17,85.72 23.01,85.72 21.42,84.13 21.42,81.28 22.06,80.64 36.67,80.64 37.94,81.91 IC2.9 44.6,81.91
LA
  Bottom 0.406: IC1.6 R17.2
LB
  Bottom 0.406: IC1.2 R18.2 89.05,83.81 85.88,86.99 36.98,86.99 34.12,84.13 30,84.13 28.09,82.23 R6.2
LC
  Bottom 0.406: IC1.8 73.81,77.78 75.08,76.51 96.67,76.51 99.21,79.05 R19.2
LD
  Bottom 0.406: R8.2 35.39,81.91 38.57,85.09 69.37,85.09 72.54,81.91 R20.2 74.45,81.91 76.99,84.45 82.39,84.45 83.97,82.86 IC1.4
LE
  Bottom 0.406: IC1.5 R21.2 81.43,82.55 80.8,83.18 77.62,83.18 75.08,80.64 71.91,80.64 68.1,84.45 48.41,84.45 47.14,83.18 47.14,81.28 46.51,80.64 40.16,80.64 38.89,79.37 R45.2
LF
  Bottom 0.406: R22.2 R5.2 25.55,82.55 27.78,84.77 33.49,84.77 36.35,87.62 87.78,87.62 91.59,83.81 IC1.1
LG
  Bottom 0.406: IC1.3 R23.2 86.51,83.18 83.97,85.72 37.3,85.72 35.08,83.5 31.9,83.5 30.63,82.23 R7.2
LH
  Bottom 0.406: IC1.7 76.35,78.1 77.3,77.15 92.55,77.15 94.13,78.74 R24.2
N$1
  Bottom 0.356: R6.1 "-".1
N$2
  Bottom 0.356: "+".1 R5.1
N$3
  Bottom 0.356: R7.1 "SET".1
N$4
  Bottom 0.406: C6.1 R15.2
N$5
  Bottom 0.406: BUZ.1 C6.2
N$6
  Bottom 0.406: G1.- 104.29,21.59 104.16,21.72 G2.+
N$7
  Bottom 0.406: LED1.K 100.48,14.6 96.67,18.41 R32.2
N$8
  Bottom 0.406: LED2.K 83.34,12.06 94.13,22.85 R35.2
N$9
  Bottom 0.356: R8.1 "F".1
N$10
  Bottom 0.406: U1.3 U2.3 35.71,14.6 40.16,19.04 40.16,23.17 48.41,31.43 48.41,33.97 49.68,35.24 49.68,50.79 50.95,52.07 R11.1
N$11
  Bottom 0.406: Q1.2 IC1.28
N$12
  Bottom 0.406: 58.89,26.66 G2.- G4.+
N$13
  Bottom 0.406: Q1.1 IC1.29
N$14
  Bottom 0.406: D4.C D5.A
N$15
  Bottom 0.406: D6.A D14.C
N$16
  Bottom 0.406: LED3.K 70,14.6 76.67,21.27 82.39,21.27 86.51,25.4 R37.2
N$17
  Bottom 0.406: VT1.1 45.12,53.13 45.87,52.38 R12.2 38.25,48.89 36.98,47.62 36.98,44.45 40.16,41.27 D2.A
N$18
  Bottom 1.016: R13.1 D2.C
N$19
  Bottom 0.406: LED4.K 59.84,14.6 67.46,22.22 67.46,24.13 71.91,28.57 75.72,28.57 78.89,31.74 R39.2
N$20
  Bottom 0.406: R28.2 D8.A C8.2 R27.2
N$21
  Bottom 0.813: R14.1 41.75,31.11 43.33,32.7 D1.A
  Bottom 1.016: IC4.GND 21.74,31.11 23.65,29.21 31.27,29.21 33.17,31.11 R14.1
N$23
  Bottom 0.406: D7.A R26.2 27.46,74.29 28.09,73.66 28.09,69.84 27.46,69.21 C7.2 28.09,67.94 28.09,62.86 R25.2
N$24
  Bottom 0.813: D3.A C3.+
  Bottom 1.27: D3.A 14.12,36.19 16.66,33.65 IC4.OUT
N$25
  Bottom 0.406: R16.2 100.48,74.29 99.21,75.56 73.18,75.56 71.27,77.47 IC1.9
N$26
  Bottom 0.406: R29.2 25.55,59.05 24.28,60.32 D9.A | D9.A R30.2 | D9.A C9.2
N$27
  Bottom 0.406: D9.C 16.66,59.68 11.58,54.6 11.58,43.81 12.22,43.18 12.22,36.19 19.84,28.57 19.84,26.03 25.55,20.32 E1.1
N$28
  Bottom 0.406: D8.C 16.66,68.57 14.76,66.67 14.76,59.37 10.63,55.56 10.63,43.49 11.26,42.86 11.26,35.87 18.89,28.25 18.89,25.71 24.28,20.32 24.28,10.79 23.01,9.52 E2.1
N$29
  Bottom 0.406: D7.C 16.03,74.29 14.76,73.02 14.76,67.94 14.12,67.31 14.12,60.32 9.36,55.56 9.36,43.49 10.31,42.54 10.31,35.55 17.93,27.93 17.93,21.59 18.57,20.95 18.57,11.43 20.47,9.52 E3.1
N$30
  Bottom 0.406: X1.2 101.75,6.98 103.02,8.25 103.02,13.96 97.63,19.36 97.63,34.29 98.26,34.92 98.26,40.95 96.67,42.54 R32.1 D10.A Q2.3
N$31  (via drill 0.8)
  Top 0.127: v83.97,42.54 v83.97,32.38
  Bottom 0.406: X3.2 71.27,6.98 69.37,8.88 66.83,8.88 65.56,10.15 65.56,13.96 66.83,15.24 68.73,15.24 75.72,22.22 82.07,22.22 83.97,24.13 v83.97,32.38 | v83.97,42.54 R37.1 D12.A Q5.3
N$32  (via drill 0.8)
  Top 0.127: v73.81,38.73 v73.81,26.03
  Bottom 0.406: v73.81,38.73 76.35,41.27 D13.A R39.1 78.89,46.03 Q6.3 | X4.2 61.11,8.25 63.02,10.15 63.02,15.24 66.19,18.41 70,18.41 73.81,22.22 v73.81,26.03
N$34
  Bottom 0.406: R43.1 DD1.8 23.01,53.97 C11.2
N$35
  Bottom 0.406: DD1.3 DD1.12 R43.2
N$36
  Bottom 0.406: DD1.2 33.17,41.27 33.17,46.35 DD1.5 33.81,47.62 34.44,48.26 34.44,51.43 36.35,53.34 38.89,53.34 40.16,54.6 40.16,58.1 40.79,58.73 41.75,58.73 41.74,58.74 Q7.1
N$37
  Bottom 0.406: D16.C DD1.13
N$38
  Bottom 0.406: R44.2 D15.C 64.92,60.32 64.92,66.03 63.65,67.31 46.51,67.31 44.6,65.4 44.6,62.86 43.97,62.23 40.16,62.23 38.89,60.96 38.89,55.88 37.62,54.6 35.08,54.6 33.17,52.7 33.17,50.79 32.54,50.16 DD1.6 29.36,50.16 26.82,47.62 DD1.10
N$39  (via drill 0.8)
  Top 0.127: v16.66,19.68 v28.09,19.68
  Bottom 0.406: v28.09,19.68 R41.1 | v16.66,19.68 16.66,27.93 8.72,35.87 8.72,41.59 6.5,43.81 6.5,56.19 9.36,59.05 9.36,72.07 7.77,73.66 7.77,86.36 10.31,88.9 11.1
N$40
  Bottom 0.406: R33.2 95.4,6.98 96.67,5.71 X1.1
N$41
  Bottom 0.406: Q3.3 77.94,47.94 76.99,47.94 73.18,44.13 72.23,44.13 71.27,43.18 R34.1 71.32,42.49 Q4.1
N$42
  Bottom 0.406: LED2.A 82.7,17.14 R36.1 91.59,23.49 D11.C 90.32,36.19 Q4.3
N$43  (via drill 0.8)
  Top 0.127: v7.77,45.08 v14.12,45.08
  Bottom 0.406: DD1.11 R42.2 v14.12,45.08 | 13.1 15.39,92.39 8.41,85.4 8.41,75.24 10.63,73.02 10.63,58.73 7.77,55.88 v7.77,45.08
N$44
  Bottom 0.406: LED5.A 47.14,13.33 47.78,13.96 49.05,13.96 49.68,14.6 49.68,22.54 50.95,23.81 53.17,23.81 54.13,22.85 56.67,22.85 57.94,24.13 59.52,24.13 60.8,25.4 60.8,27.93 59.52,29.21 56.67,29.21 R47.1
N$45
  Bottom 0.406: Q7.3 Q8.3 45.24,59.68 45.24,61.59 45.87,62.23 46.51,62.23 47.14,62.86 47.14,65.4 48.41,66.67 58.57,66.67 59.84,65.4 59.84,62.86 59.21,62.23 59.21,51.43 60.48,50.16 R46.1 65.24,50.16 Q9.1
N$46
  Bottom 0.406: R36.2 82.7,6.98 81.43,5.71 X2.2
N$47
  Bottom 0.406: X3.1 66.19,7.62 64.29,9.52 64.29,14.6 66.83,17.14 R38.2
N$48
  Bottom 0.406: D16.A 17.3,47.62 14.76,50.16 14.76,55.88 17.93,59.05 17.93,78.74 17.3,79.37 R45.1
N$49
  Bottom 0.406: X4.1 56.03,6.98 57.94,8.88 59.84,8.88 61.75,10.79 61.75,15.24 66.19,19.68 R40.2
N$50
  Bottom 0.406: X5.1 45.87,7.62 44.6,8.88 44.6,13.33 47.14,15.87 R48.1 48.41,23.17 49.68,24.44 54.45,24.44 D17.C
N$51
  Bottom 1.27: G4.- 6.5,26.66 6.64,26.53 G5.+
N$52  (via drill 1)
  Top 0.406: v58.57,38.73 v61.11,38.73
  Bottom 0.406: v61.11,38.73 D14.A | D5.C v58.57,38.73
OUT_1
  Bottom 0.406: IC1.37 81.75,66.35 78.58,66.35 77.62,65.4 77.62,57.78 R31.1 78.89,49.84 78.89,49.85 Q3.2
OUT_2
  Bottom 0.406: IC1.36 81.43,50.16 84.92,46.67 87.78,46.67 | 87.78,46.67 87.83,46.71 Q5.1 | 87.78,46.67 88.1,46.67
OUT_3
  Bottom 0.406: IC1.35 78.89,60.32 80.48,58.73 80.48,49.21 80.8,48.89 80.8,46.99 80.8,46.98 Q6.1
OUT_4
  Bottom 0.406: IC1.34 76.35,57.78 73.81,55.24 R44.1
P_WIRE0
  Bottom 0.406: IC1.25 53.49,60.96 51.59,59.05 R9.1 50.32,59.05 49.68,58.41 49.68,52.07 48.73,51.11 48.73,35.24 47.78,34.29 47.78,31.74 39.2,23.17 39.2,20 30.63,11.43 U1.2
P_WIRE1
  Bottom 0.406: IC1.26 56.03,61.59 R10.1 51.59,56.51 52.22,55.88 52.22,52.07 50.64,50.48 50.64,35.24 49.05,33.65 49.05,31.11 41.43,23.49 41.43,18.41 38.25,15.24 U2.2
PIN_CALLS_A_E
  Bottom 0.406: 48.41,64.77 IC1.23 48.41,62.23 47.14,60.96 47.19,60.91 Q8.1
SH
  Bottom 0.406: IC2.11 IC1.16
ST
  Bottom 0.406: IC2.12 IC2.13 IC1.15
U1
  Bottom 0.406: C10.2 R29.1 R25.1 35.71,62.86 35.71,65.4 R27.1 43.33,66.67 45.24,68.57 64.92,68.57 67.46,66.03 67.46,60.32 68.73,59.05 R31.2
VCC  (via drill 0.8)
  Top 0.127: v53.49,36.19 v45.87,36.19 | v62.38,22.22 v101.12,22.22 | v96.67,71.75 v96.67,81.91
  Bottom 0.406: IC2.10 48.41,82.55 49.68,83.81 58.57,83.81 59.84,82.55 59.84,81.28 60.48,80.64 61.75,80.64 63.02,81.91 IC2.16 | v96.67,81.91 96.67,83.18 94.13,85.72 91.59,85.72 89.05,88.26 50.32,88.26 49.68,88.9 49.68,92.07 50.32,92.71 50.32,95.88 49.05,97.15 14.12,97.15 12.85,95.88 12.1
  Bottom 0.61: Q3.1 75.76,49.89 75.72,49.84
  Bottom 0.813: DD1.14 26.82,37.46 28.73,35.55 32.54,35.55 33.81,36.82 33.81,38.1 35.39,39.68 36.98,39.68 37.94,38.73 D6.C
  Bottom 1.016: IC1.30 C4.1 66.19,52.07 | R9.2 R10.2 R11.2 63.02,52.07 66.19,52.07 | 66.19,52.07 75.08,52.07 75.72,51.43 75.72,49.84 75.72,48.89 72.23,45.4 65.24,45.4 63.65,43.81 63.65,36.51 62.38,35.24 62.38,34.29 | IC2.16 67.46,81.91 68.73,80.64 IC1.10 68.73,74.93 71.91,71.75 v96.67,71.75 97.94,71.75 101.75,67.94 R16.1 | v45.87,36.19 D6.C | 62.38,34.29 57.94,34.29 56.03,36.19 v53.49,36.19 | 62.38,34.29 v62.38,22.22
  Bottom 1.27: v101.12,22.22 101.12,53.97 101.75,54.6 R16.1 | DD1.14 D3.C
X39
  Bottom 0.406: R2*.2 87.78,59.05 89.05,60.32 R1*.1 IC1.39
X40
  Bottom 0.406: R3.1 R4.2 88.42,56.51 91.59,59.68 IC1.40

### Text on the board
Top: 37 | J
Drills: 5mm | 5mm | 10mm | 10mm | 14mm | 30mm | 30mm | 14mm | 10mm | 10mm | 10mm | 104.14mm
